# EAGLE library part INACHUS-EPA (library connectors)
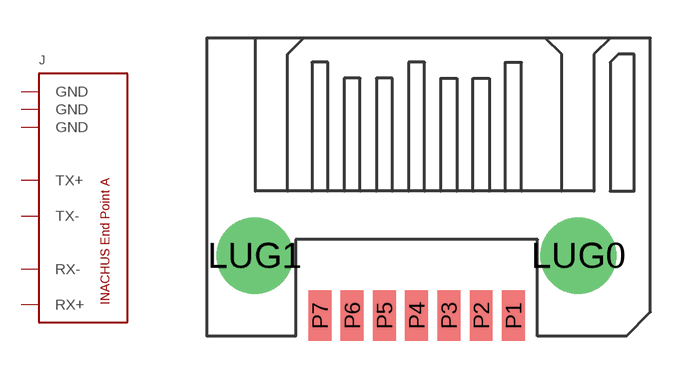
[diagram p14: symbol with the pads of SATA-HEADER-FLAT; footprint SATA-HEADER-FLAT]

Designator prefix J

## INACHUS-EPAFLAT  [SATA-HEADER-FLAT]
P1  GND  pwr
P2  RX+  out
P3  RX-  out
P4  GND  pwr
P5  TX-  in
P6  TX+  in
P7  GND  pwr

## Footprint SATA-HEADER-FLAT (pad centres in mm)
drill 1.75 pad 3 round: LUG0 6.37,0; LUG1 -6.37,0
smd 0.9 x 2: P1 3.81,-2.36; P2 2.54,-2.36; P3 1.27,-2.36; P4 0,-2.36; P5 -1.27,-2.36; P6 -2.54,-2.36; P7 -3.81,-2.36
